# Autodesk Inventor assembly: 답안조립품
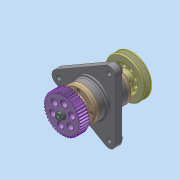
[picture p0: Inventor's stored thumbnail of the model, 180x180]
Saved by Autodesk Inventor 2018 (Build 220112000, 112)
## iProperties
Created: 2023-04
Part Number: 답안조립품
Material: 일반
Document SubType Name: Assembly
Designer: home
Author: home
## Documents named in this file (11)
- C:\Users\kimgi\Desktop\730407V1006\답안조립품.iam
- C:\Users\kimgi\Desktop\730407V1006\본체.ipt
- C:\Users\kimgi\Desktop\730407V1006\베어링 6204.ipt
- C:\Users\kimgi\Desktop\730407V1006\축.ipt
- C:\Users\kimgi\Desktop\730407V1006\커버.ipt
- C:\Users\kimgi\Desktop\730407V1006\오일 실 20 32 8.ipt
- C:\Users\kimgi\Desktop\730407V1006\볼트 M4 x 12.ipt
- C:\Users\kimgi\Desktop\730407V1006\묻힘키 5x5x16.ipt
- C:\Users\kimgi\Desktop\730407V1006\v-벨트풀리.ipt
- C:\Users\kimgi\Desktop\730407V1006\스퍼기어.ipt
- C:\Users\kimgi\Desktop\730407V1006\6각 플랜지 너트 M10.ipt
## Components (3 placed, 2 different names)
1. v-벨트풀리:1
2. 6각 플랜지 너트 M10:1
3. 6각 플랜지 너트 M10:2
